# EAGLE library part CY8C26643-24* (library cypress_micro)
The CY8C25xxx/26xxx family of Programmable System-on-Chip (PSoC) microcontrollers offers a fast core, Flash program memory and SRAM data memory with configurable analog and digital peripheral blocks in a range of convinient pinouts and memory size on one single chip.
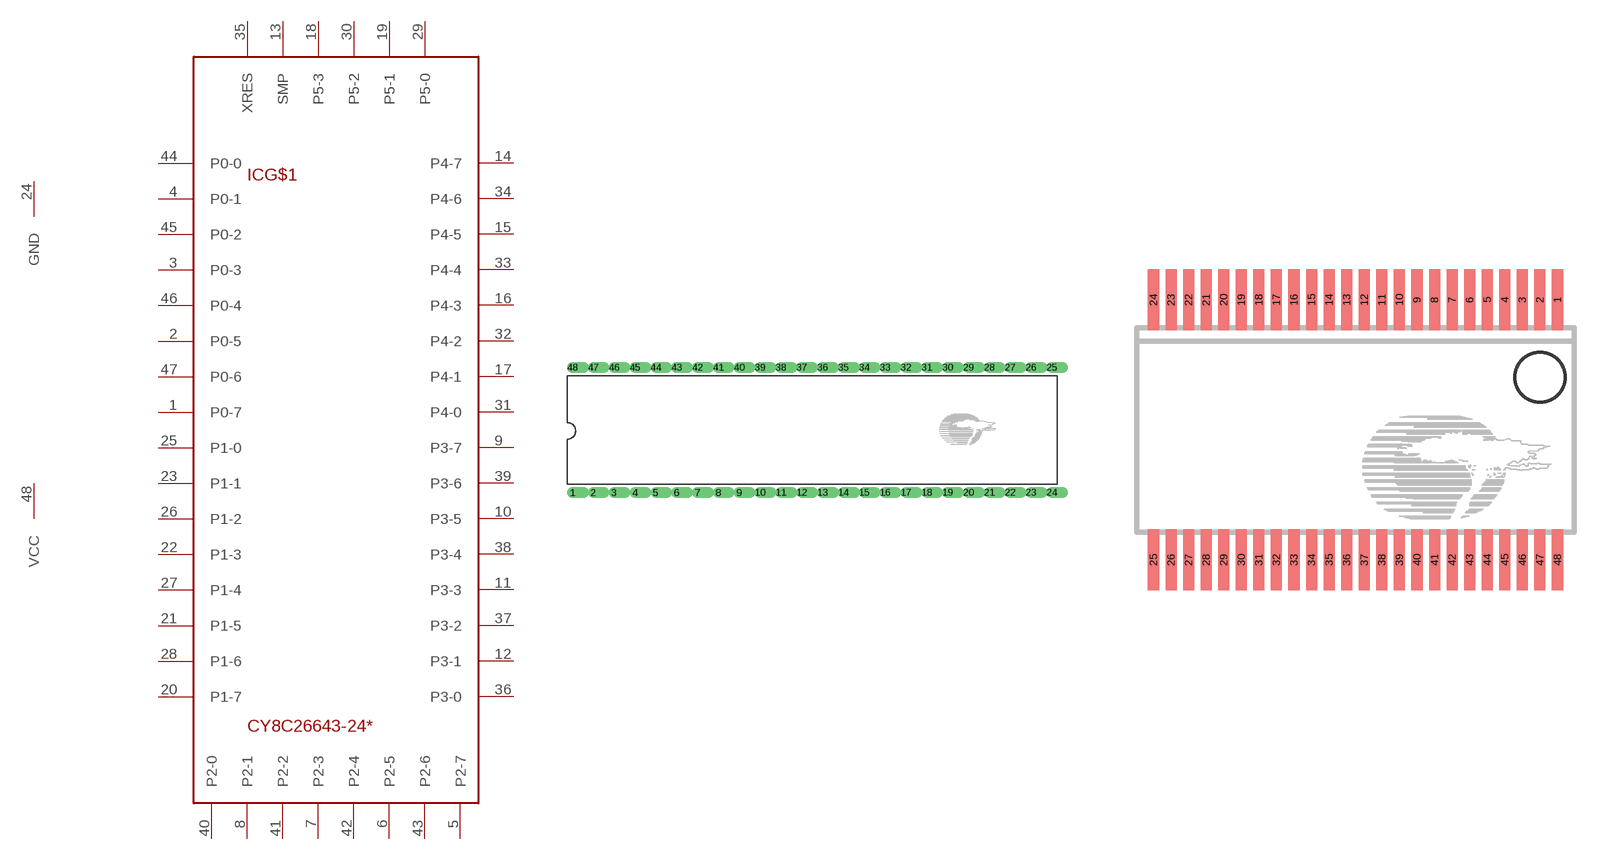
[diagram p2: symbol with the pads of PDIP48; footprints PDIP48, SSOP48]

Designator prefix IC; gates G$1=CY8C26663 G$2=GND G$3=VCC

## CY8C26643-24PI  [PDIP48]
1  G$1:P0-7
2  G$1:P0-5
3  G$1:P0-3
4  G$1:P0-1
5  G$1:P2-7
6  G$1:P2-5
7  G$1:P2-3
8  G$1:P2-1
9  G$1:P3-7
10  G$1:P3-5
11  G$1:P3-3
12  G$1:P3-1
13  G$1:SMP  out
14  G$1:P4-7
15  G$1:P4-5
16  G$1:P4-3
17  G$1:P4-1
18  G$1:P5-3
19  G$1:P5-1
20  G$1:P1-7
21  G$1:P1-5
22  G$1:P1-3
23  G$1:P1-1
24  G$2:GND  pwr
25  G$1:P1-0
26  G$1:P1-2
27  G$1:P1-4
28  G$1:P1-6
29  G$1:P5-0
30  G$1:P5-2
31  G$1:P4-0
32  G$1:P4-2
33  G$1:P4-4
34  G$1:P4-6
35  G$1:XRES  in
36  G$1:P3-0
37  G$1:P3-2
38  G$1:P3-4
39  G$1:P3-6
40  G$1:P2-0
41  G$1:P2-2
42  G$1:P2-4
43  G$1:P2-6
44  G$1:P0-0
45  G$1:P0-2
46  G$1:P0-4
47  G$1:P0-6
48  G$3:VCC  pwr

## CY8C26643-24PVI  [SSOP48]
Pads as for PDIP48

## Footprint PDIP48 (pad centres in mm)
Plastic Dual Inline Package with 48 pins
drill 0.813 offset: 1 -29.21,-7.62; 2 -26.67,-7.62; 3 -24.13,-7.62; 4 -21.59,-7.62; 5 -19.05,-7.62; 6 -16.51,-7.62; 7 -13.97,-7.62; 8 -11.43,-7.62; 9 -8.89,-7.62; 10 -6.35,-7.62; 11 -3.81,-7.62; 12 -1.27,-7.62; 13 1.27,-7.62; 14 3.81,-7.62; 15 6.35,-7.62; 16 8.89,-7.62; 17 11.43,-7.62; 18 13.97,-7.62; 19 16.51,-7.62; 20 19.05,-7.62; 21 21.59,-7.62; 22 24.13,-7.62; 23 26.67,-7.62; 24 29.21,-7.62; 25 29.21,7.62; 26 26.67,7.62; 27 24.13,7.62; 28 21.59,7.62; 29 19.05,7.62; 30 16.51,7.62; 31 13.97,7.62; 32 11.43,7.62; 33 8.89,7.62; 34 6.35,7.62; 35 3.81,7.62; 36 1.27,7.62; 37 -1.27,7.62; 38 -3.81,7.62; 39 -6.35,7.62; 40 -8.89,7.62; 41 -11.43,7.62; 42 -13.97,7.62; 43 -16.51,7.62; 44 -19.05,7.62; 45 -21.59,7.62; 46 -24.13,7.62; 47 -26.67,7.62; 48 -29.21,7.62

## Footprint SSOP48 (pad centres in mm)
Shrunk Small Outline Package with 48 pins
smd 0.4 x 2.2: 1 6.859,4.573; 2 6.223,4.573; 3 5.588,4.573; 4 4.954,4.573; 5 4.319,4.573; 6 3.683,4.573; 7 3.049,4.573; 8 2.413,4.573; 9 1.778,4.573; 10 1.143,4.573; 11 0.508,4.573; 12 -0.127,4.573; 13 -0.762,4.573; 14 -1.397,4.573; 15 -2.033,4.573; 16 -2.667,4.573; 17 -3.303,4.573; 18 -3.938,4.573; 19 -4.572,4.573; 20 -5.207,4.573; 21 -5.843,4.573; 22 -6.478,4.573; 23 -7.112,4.573; 24 -7.747,4.573; 25 -7.747,-4.827; 26 -7.112,-4.827; 27 -6.478,-4.827; 28 -5.843,-4.827; 29 -5.207,-4.827; 30 -4.572,-4.827; 31 -3.938,-4.827; 32 -3.303,-4.827; 33 -2.667,-4.827; 34 -2.033,-4.827; 35 -1.397,-4.827; 36 -0.762,-4.827; 37 -0.127,-4.827; 38 0.508,-4.827; 39 1.143,-4.827; 40 1.778,-4.827; 41 2.413,-4.827; 42 3.049,-4.827; 43 3.683,-4.827; 44 4.319,-4.827; 45 4.954,-4.827; 46 5.588,-4.827; 47 6.223,-4.827; 48 6.859,-4.827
